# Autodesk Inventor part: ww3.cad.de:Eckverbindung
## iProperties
Created: 2008-06
Material: AlMg 3;3.3535
Document SubType Name: Blech
Designer: SFl
SaveDate: 2007-10-10
SaveTime: 13:35
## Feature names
1. Bohrung1 [Hole]
2. Bohrung2 [Hole]
3. Bohrung3 [Hole]
4. Bohrung4 [Hole]
5. Bohrung5 [Hole]
6. Bohrung6 [Hole]
7. Bohrung7 [Hole]
8. Bohrung8 [Hole]
9. Bohrung9 [Hole]
10. Bohrung10 [Hole]
11. Grobblech1
12. Grobblech2
13. Biegung1
14. Grobblech5
15. Biegung4
16. Grobblech6
17. Biegung5
18. Grobblech7
19. Biegung6
20. Grobblech8
21. Biegung7
22. Grobblech9
23. Biegung8
24. Grobblech11
25. Biegung10
26. Grobblech12
27. Biegung11
28. Grobblech13
29. Biegung12
30. Grobblech14
31. Biegung13
32. Grobblech15
33. Biegung14
34. Grobblech16
35. Biegung15
36. Grobblech17
37. Biegung16
38. Grobblech18
39. Biegung17
40. Grobblech19
41. Biegung18
42. Grobblech20
43. Biegung19
44. Ausklinkung2
45. Ausklinkung3
46. Ausklinkung4
